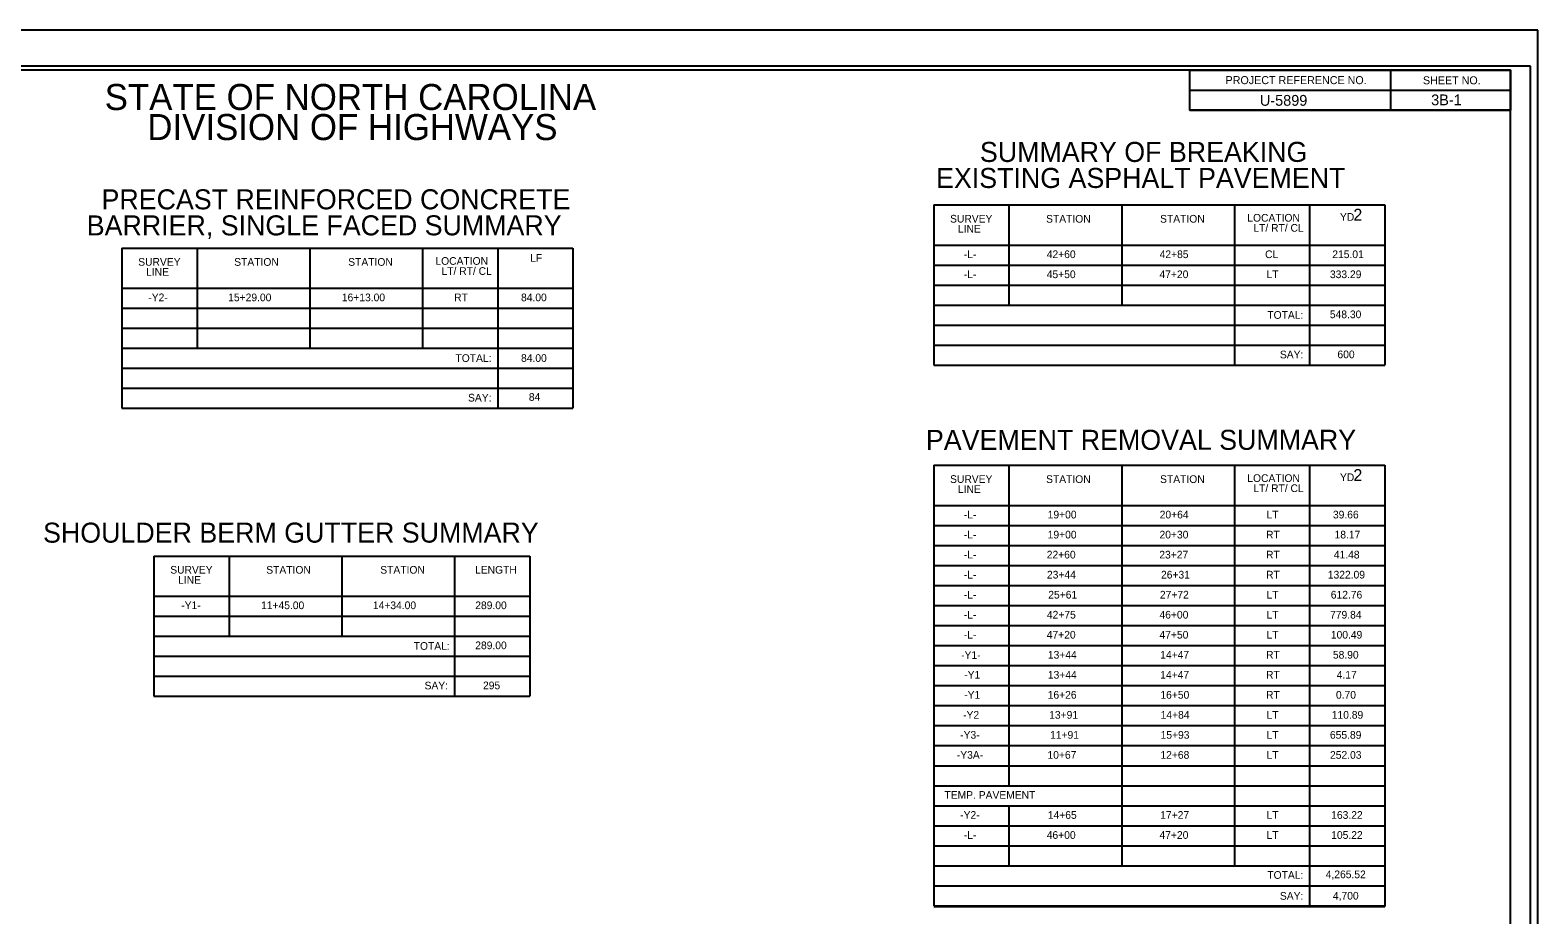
# Model space of a CAD drawing. Extents: x 1318055 to 1318380, y 620349 to 620480.
# Drawn here: x 1318198.4 to 1318292.5, y 620425.2 to 620480.4 of the extents above; entities that cross this region are included whole.
import ezdxf

# ---------------------------------------------------------------- set-up
doc = ezdxf.new("R2010")
doc.units = 0
for name, color, linetype in [('Sheet Cutting Line CELL', 7, 'Continuous'), ('Sheet Data Field CELL', 7, 'Continuous'), ('Sheet Plot Border Inside CELL', 7, 'Continuous'), ('Sheet Plot Border Outside CELL', 7, 'Continuous'), ('Sheet Summary Combination CELL', 7, 'Continuous'), ('Sheet Summary Combination Grid CELL', 7, 'Continuous')]:
    doc.layers.add(name, color=color, linetype=linetype)

msp = doc.modelspace()

# ---------------------------------------------------------------- linework, layer by layer
at = {"layer": 'Sheet Cutting Line CELL'}
msp.add_line((1318292.455, 620480.437), (1318124.055, 620480.437), dxfattribs=at)
at = {"layer": 'Sheet Plot Border Inside CELL'}
msp.add_lwpolyline([(1318292.005, 620478.192), (1318125.355, 620478.192), (1318125.355, 620372.682), (1318292.005, 620372.682)], close=True, dxfattribs=at)
at = {"layer": 'Sheet Plot Border Outside CELL'}
msp.add_lwpolyline([(1318292.455, 620480.437), (1318124.055, 620480.437), (1318124.055, 620370.437), (1318292.455, 620370.437)], close=True, dxfattribs=at)
at = {"layer": 'Sheet Summary Combination CELL'}
for p, q in [((1318283.255, 620477.932), (1318283.255, 620475.432)), ((1318270.75, 620476.682), (1318290.755, 620476.682)), ((1318270.75, 620475.432), (1318290.755, 620475.432)), ((1318268.891, 620469.52), (1318268.891, 620469.52)), ((1318269.516, 620469.51), (1318269.516, 620469.51)), ((1318270.421, 620469.53), (1318270.421, 620469.53)), ((1318270.981, 620469.52), (1318270.981, 620469.52)), ((1318218.232, 620466.827), (1318218.232, 620466.827)), ((1318218.857, 620466.817), (1318218.857, 620466.817)), ((1318219.762, 620466.837), (1318219.762, 620466.837)), ((1318220.322, 620466.827), (1318220.322, 620466.827)), ((1318268.891, 620453.27), (1318268.891, 620453.27)), ((1318269.516, 620453.26), (1318269.516, 620453.26)), ((1318270.421, 620453.28), (1318270.421, 620453.28)), ((1318270.981, 620453.27), (1318270.981, 620453.27)), ((1318220.231, 620447.608), (1318220.231, 620447.608)), ((1318220.856, 620447.598), (1318220.856, 620447.598)), ((1318221.761, 620447.618), (1318221.761, 620447.618)), ((1318222.321, 620447.608), (1318222.321, 620447.608))]:
    msp.add_line(p, q, dxfattribs=at)
for points in [[(1318290.755, 620477.937), (1318140.755, 620477.937), (1318140.755, 620372.937), (1318290.755, 620372.937)], [(1318270.75, 620477.937), (1318290.755, 620477.937), (1318290.755, 620475.432), (1318270.75, 620475.432)]]:
    msp.add_lwpolyline(points, close=True, dxfattribs=at)
at = {"layer": 'Sheet Summary Combination Grid CELL'}
for p, q in [((1318254.766, 620469.525), (1318282.901, 620469.525)), ((1318254.766, 620469.525), (1318254.766, 620459.525)), ((1318259.456, 620469.525), (1318259.456, 620463.275)), ((1318266.491, 620469.525), (1318266.491, 620463.275)), ((1318273.521, 620469.525), (1318273.521, 620459.525)), ((1318278.211, 620469.525), (1318278.211, 620459.525)), ((1318282.901, 620469.525), (1318282.901, 620459.525)), ((1318204.107, 620466.832), (1318232.242, 620466.832)), ((1318204.107, 620466.832), (1318204.107, 620456.832)), ((1318208.797, 620466.832), (1318208.797, 620460.582)), ((1318215.832, 620466.832), (1318215.832, 620460.582)), ((1318222.862, 620466.832), (1318222.862, 620460.582)), ((1318227.552, 620466.832), (1318227.552, 620456.832)), ((1318232.242, 620466.832), (1318232.242, 620456.832)), ((1318254.766, 620467.025), (1318282.901, 620467.025)), ((1318254.766, 620465.775), (1318282.901, 620465.775)), ((1318204.107, 620464.332), (1318232.242, 620464.332)), ((1318254.766, 620464.525), (1318282.901, 620464.525)), ((1318204.107, 620463.082), (1318232.242, 620463.082)), ((1318254.766, 620463.275), (1318282.901, 620463.275)), ((1318204.107, 620461.832), (1318232.242, 620461.832)), ((1318254.766, 620462.025), (1318282.901, 620462.025)), ((1318204.107, 620460.582), (1318232.242, 620460.582)), ((1318204.107, 620460.582), (1318232.242, 620460.582)), ((1318254.766, 620460.775), (1318282.901, 620460.775)), ((1318204.107, 620459.332), (1318232.242, 620459.332)), ((1318254.766, 620459.525), (1318282.901, 620459.525)), ((1318204.107, 620458.082), (1318232.242, 620458.082)), ((1318204.107, 620456.832), (1318232.242, 620456.832)), ((1318254.766, 620453.275), (1318282.901, 620453.275)), ((1318254.766, 620453.275), (1318254.766, 620425.775)), ((1318259.456, 620453.275), (1318259.456, 620433.275)), ((1318266.491, 620453.275), (1318266.491, 620428.275)), ((1318273.521, 620453.275), (1318273.521, 620428.275)), ((1318278.211, 620453.275), (1318278.211, 620425.775)), ((1318282.901, 620453.275), (1318282.901, 620425.733)), ((1318254.766, 620450.775), (1318282.901, 620450.775)), ((1318254.766, 620449.525), (1318282.901, 620449.525)), ((1318206.106, 620447.613), (1318229.551, 620447.613)), ((1318206.106, 620447.613), (1318206.106, 620438.863)), ((1318210.796, 620447.613), (1318210.796, 620442.613)), ((1318217.831, 620447.613), (1318217.831, 620442.613)), ((1318224.861, 620447.613), (1318224.861, 620438.863)), ((1318229.551, 620447.613), (1318229.551, 620438.863)), ((1318254.766, 620448.275), (1318282.901, 620448.275)), ((1318254.766, 620447.025), (1318282.901, 620447.025)), ((1318254.766, 620445.775), (1318282.901, 620445.775)), ((1318206.106, 620445.113), (1318229.551, 620445.113)), ((1318254.766, 620444.525), (1318282.901, 620444.525)), ((1318206.106, 620443.863), (1318229.551, 620443.863)), ((1318254.766, 620443.275), (1318282.901, 620443.275)), ((1318206.106, 620442.613), (1318229.551, 620442.613)), ((1318206.106, 620442.613), (1318229.551, 620442.613)), ((1318254.766, 620442.025), (1318282.901, 620442.025)), ((1318206.106, 620441.363), (1318229.551, 620441.363)), ((1318206.106, 620441.363), (1318229.551, 620441.363)), ((1318254.766, 620440.775), (1318282.901, 620440.775)), ((1318206.106, 620440.113), (1318229.551, 620440.113)), ((1318206.106, 620440.113), (1318229.551, 620440.113)), ((1318254.766, 620439.525), (1318282.901, 620439.525)), ((1318206.106, 620438.863), (1318229.551, 620438.863)), ((1318254.766, 620438.275), (1318282.901, 620438.275)), ((1318254.766, 620437.025), (1318282.901, 620437.025)), ((1318254.766, 620435.775), (1318282.901, 620435.775)), ((1318254.766, 620434.525), (1318282.901, 620434.525)), ((1318254.766, 620434.525), (1318282.901, 620434.525)), ((1318254.766, 620434.525), (1318282.901, 620434.525)), ((1318254.766, 620433.275), (1318282.901, 620433.275)), ((1318254.766, 620432.025), (1318282.901, 620432.025)), ((1318259.456, 620432.025), (1318259.456, 620428.275)), ((1318254.766, 620430.775), (1318282.901, 620430.775)), ((1318254.766, 620429.525), (1318282.901, 620429.525)), ((1318254.766, 620428.275), (1318282.901, 620428.275)), ((1318254.766, 620427.025), (1318282.901, 620427.025)), ((1318254.766, 620425.775), (1318282.901, 620425.775)), ((1318254.766, 620425.733), (1318282.901, 620425.733))]:
    msp.add_line(p, q, dxfattribs=at)

# ---------------------------------------------------------------- texts
at = {"layer": 'Sheet Data Field CELL'}
for s, p in [('U-5899', (1318275.11, 620475.717)), ('3B-1', (1318285.799, 620475.747))]:
    msp.add_text(s, height=0.675, dxfattribs=at).set_placement(p)
at = {"layer": 'Sheet Summary Combination CELL'}
for s, height, p in [('PROJECT REFERENCE NO.', 0.50001, (1318272.97, 620477.067)), ('SHEET NO.', 0.5, (1318285.285, 620477.057)), ('STATE OF NORTH CAROLINA', 1.62501, (1318203.03, 620475.452)), ('DIVISION OF HIGHWAYS', 1.62501, (1318205.69, 620473.577)), ('SURVEY', 0.48, (1318255.781, 620468.426)), ('LINE', 0.48, (1318256.271, 620467.796)), ('STATION', 0.48, (1318261.771, 620468.421)), ('STATION', 0.48, (1318268.885, 620468.423)), ('LOCATION', 0.48, (1318274.326, 620468.485)), ('LT/ RT/ CL', 0.48, (1318274.705, 620467.855)), ('SURVEY', 0.48, (1318205.122, 620465.733)), ('STATION', 0.48, (1318211.112, 620465.728)), ('STATION', 0.48, (1318218.226, 620465.729)), ('LOCATION', 0.48, (1318223.667, 620465.791)), ('-L-', 0.48, (1318256.639, 620466.208)), ('42+60', 0.48, (1318261.812, 620466.208)), ('42+85', 0.48, (1318268.856, 620466.208)), ('CL', 0.48, (1318275.436, 620466.208)), ('215.01', 0.48, (1318279.63, 620466.208)), ('LINE', 0.48, (1318205.612, 620465.103)), ('LT/ RT/ CL', 0.48, (1318224.046, 620465.161)), ('-L-', 0.48, (1318256.639, 620464.958)), ('45+50', 0.48, (1318261.812, 620464.958)), ('47+20', 0.48, (1318268.847, 620464.958)), ('LT', 0.48, (1318275.524, 620464.958)), ('333.29', 0.48, (1318279.482, 620464.958)), ('-Y2-', 0.48, (1318205.752, 620463.515)), ('15+29.00', 0.48, (1318210.736, 620463.515)), ('16+13.00', 0.48, (1318217.828, 620463.515)), ('RT', 0.48, (1318224.836, 620463.515)), ('84.00', 0.48, (1318229.008, 620463.515)), ('TOTAL:', 0.48, (1318275.576, 620462.42)), ('548.30', 0.48, (1318279.478, 620462.458)), ('TOTAL:', 0.48, (1318224.917, 620459.727)), ('84.00', 0.48, (1318229.008, 620459.73)), ('SAY:', 0.48, (1318276.36, 620459.949)), ('600', 0.48, (1318279.952, 620459.958)), ('SAY:', 0.48, (1318225.701, 620457.255)), ('84', 0.48, (1318229.496, 620457.3)), ('SURVEY', 0.48, (1318255.781, 620452.176)), ('STATION', 0.48, (1318261.771, 620452.171)), ('STATION', 0.48, (1318268.885, 620452.173)), ('LOCATION', 0.48, (1318274.326, 620452.235)), ('LT/ RT/ CL', 0.48, (1318274.705, 620451.605)), ('LINE', 0.48, (1318256.271, 620451.546)), ('-L-', 0.48, (1318256.639, 620449.958)), ('19+00', 0.48, (1318261.869, 620449.958)), ('20+64', 0.48, (1318268.86, 620449.958)), ('LT', 0.48, (1318275.524, 620449.958)), ('39.66', 0.48, (1318279.669, 620449.958)), ('-L-', 0.48, (1318256.639, 620448.708)), ('19+00', 0.48, (1318261.869, 620448.708)), ('20+30', 0.48, (1318268.847, 620448.708)), ('RT', 0.48, (1318275.496, 620448.708)), ('18.17', 0.48, (1318279.771, 620448.708)), ('-L-', 0.48, (1318256.639, 620447.458)), ('22+60', 0.48, (1318261.812, 620447.458)), ('23+27', 0.48, (1318268.836, 620447.458)), ('RT', 0.48, (1318275.496, 620447.458)), ('41.48', 0.48, (1318279.725, 620447.458)), ('SURVEY', 0.48, (1318207.121, 620446.514)), ('STATION', 0.48, (1318213.111, 620446.509)), ('STATION', 0.48, (1318220.225, 620446.511)), ('LENGTH', 0.48, (1318226.138, 620446.511)), ('-L-', 0.48, (1318256.639, 620446.208)), ('23+44', 0.48, (1318261.825, 620446.208)), ('26+31', 0.48, (1318268.942, 620446.208)), ('RT', 0.48, (1318275.496, 620446.208)), ('1322.09', 0.48, (1318279.349, 620446.208)), ('LINE', 0.48, (1318207.611, 620445.884)), ('-Y1-', 0.48, (1318207.808, 620444.296)), ('11+45.00', 0.48, (1318212.787, 620444.296)), ('14+34.00', 0.48, (1318219.765, 620444.296)), ('289.00', 0.48, (1318226.152, 620444.296)), ('-L-', 0.48, (1318256.639, 620444.958)), ('25+61', 0.48, (1318261.907, 620444.958)), ('27+72', 0.48, (1318268.873, 620444.958)), ('LT', 0.48, (1318275.524, 620444.958)), ('612.76', 0.48, (1318279.536, 620444.958)), ('-L-', 0.48, (1318256.639, 620443.708)), ('42+75', 0.48, (1318261.821, 620443.708)), ('46+00', 0.48, (1318268.847, 620443.708)), ('LT', 0.48, (1318275.524, 620443.708)), ('779.84', 0.48, (1318279.491, 620443.708)), ('-L-', 0.48, (1318256.639, 620442.458)), ('47+20', 0.48, (1318261.812, 620442.458)), ('47+50', 0.48, (1318268.847, 620442.458)), ('LT', 0.48, (1318275.524, 620442.458)), ('100.49', 0.48, (1318279.539, 620442.458)), ('TOTAL:', 0.48, (1318222.312, 620441.758)), ('289.00', 0.48, (1318226.152, 620441.796)), ('-Y1-', 0.48, (1318256.468, 620441.19)), ('13+44', 0.48, (1318261.882, 620441.208)), ('14+47', 0.48, (1318268.893, 620441.208)), ('RT', 0.48, (1318275.496, 620441.208)), ('58.90', 0.48, (1318279.667, 620441.208)), ('-Y1', 0.48, (1318256.663, 620439.958)), ('13+44', 0.48, (1318261.882, 620439.958)), ('14+47', 0.48, (1318268.893, 620439.958)), ('RT', 0.48, (1318275.496, 620439.958)), ('4.17', 0.48, (1318279.904, 620439.958)), ('SAY:', 0.48, (1318222.99, 620439.287)), ('295', 0.48, (1318226.636, 620439.296)), ('-Y1', 0.48, (1318256.663, 620438.708)), ('16+26', 0.48, (1318261.871, 620438.708)), ('16+50', 0.48, (1318268.904, 620438.708)), ('RT', 0.48, (1318275.496, 620438.708)), ('0.70', 0.48, (1318279.857, 620438.708)), ('-Y2', 0.48, (1318256.594, 620437.458)), ('13+91', 0.48, (1318261.964, 620437.458)), ('14+84', 0.48, (1318268.917, 620437.458)), ('LT', 0.48, (1318275.524, 620437.458)), ('110.89', 0.48, (1318279.596, 620437.458)), ('-Y3-', 0.48, (1318256.411, 620436.208)), ('11+91', 0.48, (1318262.021, 620436.208)), ('15+93', 0.48, (1318268.915, 620436.208)), ('LT', 0.48, (1318275.524, 620436.208)), ('655.89', 0.48, (1318279.482, 620436.208)), ('-Y3A-', 0.48, (1318256.203, 620434.958)), ('10+67', 0.48, (1318261.858, 620434.958)), ('12+68', 0.48, (1318268.905, 620434.958)), ('LT', 0.48, (1318275.524, 620434.958)), ('252.03', 0.48, (1318279.488, 620434.958)), ('TEMP. PAVEMENT', 0.48, (1318255.43, 620432.458)), ('-Y2-', 0.48, (1318256.411, 620431.208)), ('14+65', 0.48, (1318261.879, 620431.208)), ('17+27', 0.48, (1318268.893, 620431.208)), ('LT', 0.48, (1318275.524, 620431.208)), ('163.22', 0.48, (1318279.561, 620431.208)), ('-L-', 0.48, (1318256.639, 620429.958)), ('46+00', 0.48, (1318261.812, 620429.958)), ('47+20', 0.48, (1318268.847, 620429.958)), ('LT', 0.48, (1318275.524, 620429.958)), ('105.22', 0.48, (1318279.561, 620429.958)), ('TOTAL:', 0.48, (1318275.576, 620427.463)), ('4,265.52', 0.48, (1318279.219, 620427.501)), ('4,700', 0.48, (1318279.667, 620426.167)), ('SAY:', 0.48, (1318276.36, 620426.157))]:
    msp.add_text(s, height=height, dxfattribs=at).set_placement(p)
for s, p in [('SUMMARY OF BREAKING', (1318257.642, 620472.209)), ('EXISTING ASPHALT PAVEMENT', (1318254.906, 620470.584)), ('PRECAST REINFORCED CONCRETE', (1318202.831, 620469.25)), ('BARRIER, SINGLE FACED SUMMARY', (1318201.911, 620467.624)), ('PAVEMENT REMOVAL SUMMARY', (1318254.274, 620454.237)), ('SHOULDER BERM GUTTER SUMMARY', (1318199.185, 620448.445))]:
    msp.add_text(s, height=1.25001, rotation=0.01193, dxfattribs=at).set_placement(p)
at = {"layer": 'Sheet Summary Combination Grid CELL'}
for s, height, p in [('YD', 0.48, (1318280.107, 620468.537)), ('2', 0.75, (1318280.944, 620468.537)), ('LF', 0.48, (1318229.579, 620465.979)), ('2', 0.75, (1318280.944, 620452.287)), ('YD', 0.48, (1318280.107, 620452.287))]:
    msp.add_text(s, height=height, dxfattribs=at).set_placement(p)

doc.saveas('drawing.dxf')
